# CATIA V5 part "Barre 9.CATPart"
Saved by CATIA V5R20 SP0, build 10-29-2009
Part number: Barre 9
Bounding box of the stored display mesh (mm): x -9.99 to 404.661, y 160.01 to 323.639, z -10 to 0
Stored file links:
  C:\Users\Matthieu\Desktop\IFMA\Cours 2A\Thinkmotion\Projet_IAO_714_Matthieu_Perrusset\Barre 9.CATPart
  C:\Users\Matthieu\Desktop\IFMA\Cours 2A\Thinkmotion\Ass_skl_IAO.CATProduct
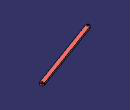
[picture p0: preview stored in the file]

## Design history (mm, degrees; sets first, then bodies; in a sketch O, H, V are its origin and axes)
AxisSystem1: origin (0, 0, 0), X (1, 0, 0), Y (0, 1, 0), Z (0, 0, 1)
Set1
  Plane1 "Plan_Ref": linked copy from another document
  Line1 "Barre_10": linked copy from another document
  Line2 "Axe_Pivot_b9b1": linked copy from another document
  Line3 "Axe_Pivot_b9b7": linked copy from another document
Body1 (main body)
  Sketch1 on Plane1, origin (0, 0, 0), H (1, 0, 0), V (0, 1, 0)
    line L1 (-3.4202, 179.3969) -> (391.2507, 323.0454)
    arc A1 centre (394.6709, 313.6485) radius 10 from (391.2507, 323.0454) to (398.0911, 304.2515) cw
    point P3 (394.6709, 313.6485)
    line L2 (398.0911, 304.2515) -> (3.4202, 160.6031)
    arc A2 centre (0, 170) radius 10 from (3.4202, 160.6031) to (-3.4202, 179.3969) cw
    point P6 (0, 170)
    reference projected line E1 (0, 170) -> (394.6709, 313.6485) from Line1
    reference projected line E2 (0, 170) -> (394.6709, 313.6485) from Line1
    reference projected line E3 (0, 170) -> (394.6709, 313.6485) from Line1
    reference projected line E4 (0, 170) -> (394.6709, 313.6485) from Line1
    reference projected point E5 (394.6709, 313.6485) from Line2
    reference projected point E6 (0, 170) from Line3
    circle A3 centre (0, 170) radius 5
    circle A4 centre (394.6709, 313.6485) radius 5
    distance L1 E3 = 10
    distance E4 L2 = 10
    distance P6 A2 = 10
    distance A1 P3 = 10
    radius A3 = 5
    radius A4 = 5
    parallelism: L2 L1, L1 E1, E2 L2
    coincidence: P3 E5, P6 E6
  Pad1: profile Sketch1, direction (0, 0, 1), length 0, opposite side length 10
